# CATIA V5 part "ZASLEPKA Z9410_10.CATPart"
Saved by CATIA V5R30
Part number: ZASLEPKA Z9410/10
Bounding box of the stored display mesh (mm): x -3 to 6, y -7 to 7, z -7 to 7
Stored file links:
  C:\Users\ondra\Desktop\PŘÍLOHA P III\CATIA\ZASLEPKA Z9410_10.CATPart
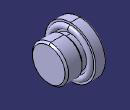
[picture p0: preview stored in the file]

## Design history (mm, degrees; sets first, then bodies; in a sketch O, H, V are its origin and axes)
Set1
  DatumSurface1 to DatumSurface25 "Z9410/10"
  Join1: Elements (DatumSurface1; DatumSurface2; DatumSurface3; DatumSurface4; DatumSurface5; DatumSurface6; DatumSurface7; DatumSurface8; DatumSurface9; DatumSurface10; DatumSurface11; DatumSurface12; DatumSurface13; DatumSurface14; DatumSurface15; DatumSurface16; DatumSurface17; DatumSurface18; DatumSurface19; DatumSurface20; DatumSurface21; DatumSurface22; DatumSurface23; DatumSurface24; DatumSurface25)
Body1 (main body)
  CloseSurface1: CloseElement Join1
